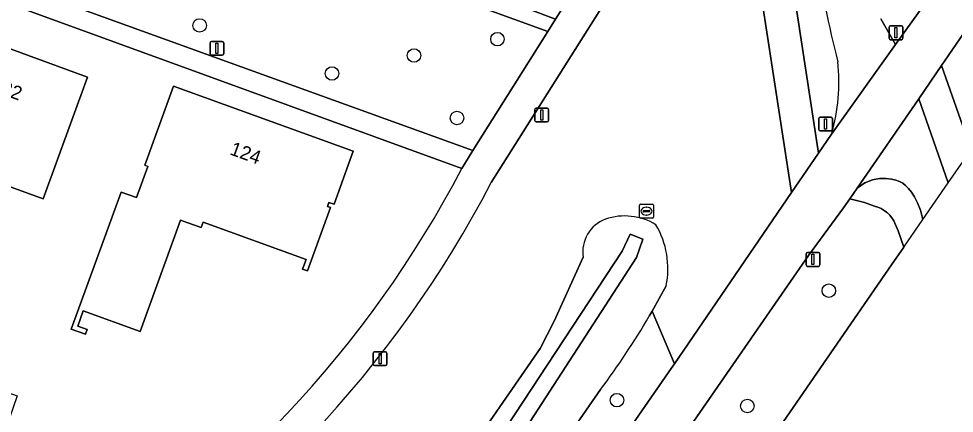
# Model space of a CAD drawing. Extents: x 155275 to 156265, y 382654 to 383635.
# Drawn here: x 156017.2 to 156085, y 382858.7 to 382887.3 of the extents above; entities that cross this region are included whole.
import ezdxf

# ---------------------------------------------------------------- set-up
doc = ezdxf.new("R2010")
doc.units = 0
for name, color, linetype in [('IMGEO_Berm_groen', 7, 'Continuous'), ('IMGEO_Boom', 7, 'Continuous'), ('IMGEO_Erf', 7, 'Continuous'), ('IMGEO_Fietspad_gesloten', 7, 'Continuous'), ('IMGEO_Groenvoorziening', 7, 'Continuous'), ('IMGEO_Lichtmast', 7, 'Continuous'), ('IMGEO_Loofbos', 7, 'Continuous'), ('IMGEO_Muur', 7, 'Continuous'), ('IMGEO_Oever', 7, 'Continuous'), ('IMGEO_Pand', 7, 'Continuous'), ('IMGEO_Pand_nummerreeks', 7, 'Continuous'), ('IMGEO_Rijbaan_lokaal_gesloten', 7, 'Continuous'), ('IMGEO_Rioolput', 7, 'Continuous'), ('IMGEO_Verkeersbordpaal', 7, 'Continuous'), ('IMGEO_Voetpad_open', 7, 'Continuous'), ('IMGEO_Waterloop', 7, 'Continuous')]:
    doc.layers.add(name, color=color, linetype=linetype)

msp = doc.modelspace()

# ---------------------------------------------------------------- linework, layer by layer
at = {"layer": 'IMGEO_Berm_groen'}
for points in [[(156079.66, 382887.343), (156080.716, 382885.461), (156082.651, 382888.154)], [(155986.514, 382749.083), (156014.734, 382790.495), (156047.177, 382837.009), (156064.466, 382861.974), (156064.698, 382862.314), (156063.065, 382866.115), (156062.862, 382865.755)], [(156059.34, 382860.43), (156000, 382774.875), (155980.085, 382745.904)]]:
    msp.add_lwpolyline(points, dxfattribs=at)
msp.add_lwpolyline([(156084.535, 382875.43), (156086.196, 382877.839), (156084.062, 382883.952), (156082.398, 382881.536)], close=True, dxfattribs=at)
msp.add_arc((156010.234, 382896.737), 61.071, 323.52277, 329.51525, dxfattribs=at)
at = {"layer": 'IMGEO_Boom'}
for centre in [(156030.272, 382886.856), (156051.859, 382885.857), (156045.814, 382884.671), (156039.869, 382883.369), (156048.927, 382880.135), (156075.884, 382867.609), (156060.522, 382859.665), (156069.98, 382859.243)]:
    msp.add_circle(centre, 0.489, dxfattribs=at)
at = {"layer": 'IMGEO_Erf'}
for points in [[(156045.075, 382959.998), (156041.929, 382961.201), (156013.02, 382971.678), (156002.893, 382944.069), (156002.495, 382942.881), (156019.157, 382936.752), (156019.126, 382936.628), (156034.624, 382930.96), (156034.689, 382931.086), (156052.26, 382924.735), (156049.961, 382918.346), (156000.148, 382936.433), (155991.066, 382911.384), (156005.755, 382906.062), (156030.725, 382896.891), (156056.081, 382887.309), (156064.322, 382900.379)], [(156049.271, 382876.469), (155986.733, 382899.275), (155985.513, 382896.209), (155977.474, 382874.314), (156011.194, 382862.059), (156017.047, 382859.976), (156014.804, 382853.502), (156014.672, 382853.55), (155989.659, 382862.664), (155989.671, 382862.757), (155975.249, 382867.763), (155964.586, 382839.123)]]:
    msp.add_lwpolyline(points, dxfattribs=at)
for points in [[(156018.937, 382874.268), (156011.075, 382877.127), (156008.041, 382868.784), (156006.026, 382869.517), (156008.951, 382877.562), (156009.749, 382877.272), (156009.857, 382877.57), (156009.742, 382877.612), (156012.953, 382886.451), (156022.145, 382883.089)], [(156025.959, 382864.645), (156021.842, 382866.141), (156021.443, 382865.041), (156022.129, 382864.792), (156022.003, 382864.444), (156020.969, 382864.82), (156024.582, 382874.764), (156025.691, 382874.361), (156026.515, 382876.626), (156026.298, 382876.704), (156028.389, 382882.456), (156041.398, 382877.728), (156040.023, 382873.884), (156039.649, 382874.017), (156039.541, 382873.718), (156039.757, 382873.639), (156038.092, 382869.045), (156037.734, 382869.175), (156037.987, 382869.871), (156030.525, 382872.583), (156030.381, 382872.188), (156029.423, 382872.537), (156028.896, 382872.728)]]:
    msp.add_lwpolyline(points, close=True, dxfattribs=at)
msp.add_arc((155979.211, 382912.976), 79.001, 300.67593, 332.47672, dxfattribs=at)
at = {"layer": 'IMGEO_Fietspad_gesloten'}
for points in [[(156082.398, 382881.536), (156084.062, 382883.952), (156086.982, 382888.192), (156088.437, 382890.305), (156091.194, 382894.308), (156094.99, 382899.819), (156096.461, 382901.955), (156095.373, 382906.504), (156091.11, 382900.353), (156089.894, 382898.497), (156087.194, 382894.668), (156085.596, 382892.423), (156082.651, 382888.154), (156080.716, 382885.461), (156076.075, 382878.967), (156075.126, 382877.579), (156073.179, 382874.729), (156064.698, 382862.314), (156064.466, 382861.974), (156047.177, 382837.009), (156014.734, 382790.495), (155986.514, 382749.083)], [(156076.075, 382878.967), (156080.716, 382885.461), (156079.66, 382887.343)], [(155984.634, 382740.15), (155989.627, 382747.079), (156025.11, 382799.188), (156066.088, 382858.148), (156074.411, 382870.169), (156076.941, 382873.612), (156077.401, 382874.28), (156077.93, 382875.048), (156082.398, 382881.536)], [(156082.709, 382872.779), (156084.535, 382875.43), (156082.398, 382881.536), (156077.93, 382875.048), (156078.493, 382875.43), (156079.039, 382875.649), (156079.552, 382875.74), (156080.017, 382875.743), (156080.418, 382875.694), (156080.744, 382875.622), (156081.011, 382875.528), (156081.237, 382875.404), (156081.442, 382875.24), (156081.647, 382875.031), (156081.866, 382874.765), (156082.094, 382874.425), (156082.317, 382873.994), (156082.526, 382873.452), (156082.708, 382872.781), (156082.709, 382872.779)]]:
    msp.add_lwpolyline(points, dxfattribs=at)
for centre, radius, start, end in [((156152.299, 382903.499), 78.179, 182.47954, 194.27589), ((156063.087, 382882.749), 13.527, 343.76588, 6.24853)]:
    msp.add_arc(centre, radius, start, end, dxfattribs=at)
at = {"layer": 'IMGEO_Groenvoorziening'}
for points in [[(156071.646, 382909.49), (156070.296, 382909.238), (156075.126, 382877.579), (156076.075, 382878.967)], [(156000, 382752.752), (156080.435, 382869.483), (156081.325, 382870.775), (156080.907, 382871.954), (156080.597, 382872.668), (156080.458, 382872.887), (156080.436, 382872.914), (156080.295, 382873.088), (156080.128, 382873.251), (156080.11, 382873.269), (156080.058, 382873.313), (156079.905, 382873.428), (156079.683, 382873.562), (156079.447, 382873.67), (156079.201, 382873.75), (156078.46, 382873.996), (156077.401, 382874.28), (156076.941, 382873.612), (156074.411, 382870.169), (156066.088, 382858.148)]]:
    msp.add_lwpolyline(points, dxfattribs=at)
for points in [[(156022.063, 382898.577), (156018.644, 382889.178), (156050.086, 382877.791), (156055.519, 382886.418)], [(156081.326, 382870.772), (156081.325, 382870.775), (156080.435, 382869.483), (156000, 382752.752), (156033.182, 382800.905)]]:
    msp.add_lwpolyline(points, close=True, dxfattribs=at)
for centre, radius, start, end in [((156152.299, 382903.499), 78.179, 182.47954, 194.27589), ((156063.087, 382882.749), 13.527, 343.76588, 6.24853)]:
    msp.add_arc(centre, radius, start, end, dxfattribs=at)
at = {"layer": 'IMGEO_Lichtmast'}
for p, q in [((156031.028, 382884.788), (156031.028, 382885.588)), ((156031.028, 382885.588), (156031.028, 382884.788)), ((156031.128, 382885.688), (156031.918, 382885.688)), ((156031.918, 382885.688), (156031.128, 382885.688)), ((156032.018, 382885.588), (156032.018, 382884.788)), ((156032.018, 382884.788), (156032.018, 382885.588)), ((156031.918, 382884.688), (156031.128, 382884.688)), ((156031.128, 382884.688), (156031.918, 382884.688)), ((156054.676, 382880.863), (156055.466, 382880.863)), ((156055.466, 382880.863), (156054.676, 382880.863)), ((156054.576, 382879.963), (156054.576, 382880.763)), ((156054.576, 382880.763), (156054.576, 382879.963)), ((156055.566, 382880.763), (156055.566, 382879.963)), ((156055.566, 382879.963), (156055.566, 382880.763)), ((156055.466, 382879.863), (156054.676, 382879.863)), ((156054.676, 382879.863), (156055.466, 382879.863)), ((156074.236, 382869.475), (156074.236, 382870.275)), ((156074.236, 382870.275), (156074.236, 382869.475)), ((156074.336, 382870.375), (156075.126, 382870.375)), ((156075.126, 382870.375), (156074.336, 382870.375)), ((156075.226, 382870.275), (156075.226, 382869.475)), ((156075.226, 382869.475), (156075.226, 382870.275)), ((156075.126, 382869.375), (156074.336, 382869.375)), ((156074.336, 382869.375), (156075.126, 382869.375)), ((156042.858, 382862.269), (156042.858, 382863.069)), ((156042.858, 382863.069), (156042.858, 382862.269)), ((156042.958, 382863.169), (156043.748, 382863.169)), ((156043.748, 382863.169), (156042.958, 382863.169)), ((156043.848, 382863.069), (156043.848, 382862.269)), ((156043.848, 382862.269), (156043.848, 382863.069)), ((156043.748, 382862.169), (156042.958, 382862.169)), ((156042.958, 382862.169), (156043.748, 382862.169))]:
    msp.add_line(p, q, dxfattribs=at)
for points in [[(156031.448, 382885.563), (156031.598, 382885.563), (156031.598, 382884.813), (156031.448, 382884.813), (156031.448, 382885.563)], [(156054.996, 382880.738), (156055.146, 382880.738), (156055.146, 382879.988), (156054.996, 382879.988), (156054.996, 382880.738)], [(156074.656, 382870.25), (156074.806, 382870.25), (156074.806, 382869.5), (156074.656, 382869.5), (156074.656, 382870.25)], [(156043.278, 382863.044), (156043.428, 382863.044), (156043.428, 382862.294), (156043.278, 382862.294), (156043.278, 382863.044)]]:
    msp.add_lwpolyline(points, dxfattribs=at)
for centre, start, end in [((156031.128, 382885.588), 90, 180), ((156031.128, 382885.588), 90, 180), ((156031.918, 382885.588), 0, 90), ((156031.918, 382885.588), 360, 90), ((156031.128, 382884.788), 180, 270), ((156031.128, 382884.788), 180, 270), ((156031.918, 382884.788), 270, 0), ((156031.918, 382884.788), 270, 0), ((156054.676, 382880.763), 90, 180), ((156054.676, 382880.763), 90, 180), ((156055.466, 382880.763), 0, 90), ((156055.466, 382880.763), 360, 90), ((156054.676, 382879.963), 180, 270), ((156054.676, 382879.963), 180, 270), ((156055.466, 382879.963), 270, 0), ((156055.466, 382879.963), 270, 0), ((156074.336, 382870.275), 90, 180), ((156074.336, 382870.275), 90, 180), ((156075.126, 382870.275), 0, 90), ((156075.126, 382870.275), 360, 90), ((156074.336, 382869.475), 180, 270), ((156074.336, 382869.475), 180, 270), ((156075.126, 382869.475), 270, 0), ((156075.126, 382869.475), 270, 0), ((156042.958, 382863.069), 90, 180), ((156042.958, 382863.069), 90, 180), ((156043.748, 382863.069), 0, 90), ((156043.748, 382863.069), 360, 90), ((156042.958, 382862.269), 180, 270), ((156042.958, 382862.269), 180, 270), ((156043.748, 382862.269), 270, 0), ((156043.748, 382862.269), 270, 0)]:
    msp.add_arc(centre, 0.1, start, end, dxfattribs=at)
at = {"layer": 'IMGEO_Loofbos'}
for points in [[(156064.098, 382867.956), (156063.065, 382866.115), (156064.698, 382862.314), (156073.179, 382874.729), (156069.286, 382900.053), (156068.696, 382903.893)], [(156066.49, 382899.37), (156051.412, 382875.466)], [(156054.965, 382863.418), (156055.977, 382865.399), (156058.076, 382870.033)], [(155934.35, 382725.505), (155936.692, 382725.864), (155940.946, 382726.618), (155945.166, 382727.826), (155948.196, 382728.914), (155951.784, 382730.315), (155954.364, 382731.6), (155958.769, 382734.001), (155962.634, 382736.652), (155965.967, 382739.079), (155968.671, 382741.394), (155972.439, 382745.646), (155978.599, 382754.24), (155980.796, 382757.16), (155986.725, 382765.837), (156000, 382783.894), (156054.965, 382863.418)]]:
    msp.add_lwpolyline(points, dxfattribs=at)
for centre, radius, start, end in [((155979.209, 382912.978), 81.366, 300.6869, 332.54647), ((156060.591, 382870.42), 2.545, 110.83809, 188.73927), ((156061.088, 382868.663), 4.366, 58.76089, 108.72343), ((156057.858, 382869.19), 6.361, 348.81162, 30.26365)]:
    msp.add_arc(centre, radius, start, end, dxfattribs=at)
at = {"layer": 'IMGEO_Muur'}
msp.add_lwpolyline([(156061.948, 382870.021), (156062.389, 382871.357), (156061.475, 382871.707), (156060.891, 382870.474)], dxfattribs=at)
at = {"layer": 'IMGEO_Oever'}
for points in [[(155978.096, 382748.892), (156032.148, 382826.737), (156060.891, 382870.474), (156061.475, 382871.707), (156062.389, 382871.357), (156061.948, 382870.021), (156039.407, 382835.215), (156018.939, 382805.285), (156004.138, 382783.88), (155988.541, 382761.444), (155979.267, 382747.908)], [(156058.076, 382870.033), (156055.977, 382865.399), (156054.965, 382863.418), (156000, 382783.894), (155986.725, 382765.837), (155980.796, 382757.16), (155978.599, 382754.24), (155972.439, 382745.646), (155968.671, 382741.394), (155965.967, 382739.079), (155962.634, 382736.652), (155958.769, 382734.001), (155954.364, 382731.6), (155951.784, 382730.315), (155948.196, 382728.914), (155945.166, 382727.826), (155940.946, 382726.618), (155936.692, 382725.864), (155934.35, 382725.505)], [(156062.862, 382865.755), (156063.065, 382866.115), (156064.098, 382867.956)], [(155980.085, 382745.904), (156000, 382774.875), (156059.34, 382860.43)]]:
    msp.add_lwpolyline(points, dxfattribs=at)
for centre, radius, start, end in [((156060.591, 382870.42), 2.545, 110.83809, 188.73927), ((156061.088, 382868.663), 4.366, 58.76089, 108.72343), ((156057.858, 382869.19), 6.361, 348.81162, 30.26365), ((156010.234, 382896.737), 61.071, 323.52277, 329.51525)]:
    msp.add_arc(centre, radius, start, end, dxfattribs=at)
at = {"layer": 'IMGEO_Pand'}
for points in [[(156022.145, 382883.089), (156012.953, 382886.451), (156009.742, 382877.612), (156009.857, 382877.57), (156011.075, 382877.127), (156018.937, 382874.268)], [(156022.003, 382864.444), (156022.129, 382864.792), (156021.443, 382865.041), (156021.842, 382866.141), (156025.959, 382864.645), (156028.896, 382872.728), (156029.423, 382872.537), (156030.381, 382872.188), (156030.525, 382872.583), (156037.987, 382869.871), (156037.734, 382869.175), (156038.092, 382869.045), (156039.757, 382873.639), (156039.541, 382873.718), (156039.649, 382874.017), (156040.023, 382873.884), (156041.398, 382877.728), (156028.389, 382882.456), (156026.298, 382876.704), (156026.515, 382876.626), (156025.691, 382874.361), (156024.582, 382874.764), (156020.969, 382864.82)]]:
    msp.add_lwpolyline(points, close=True, dxfattribs=at)
at = {"layer": 'IMGEO_Rijbaan_lokaal_gesloten'}
msp.add_lwpolyline([(156086.196, 382877.839), (156088.862, 382881.709), (156086.982, 382888.192), (156084.062, 382883.952)], close=True, dxfattribs=at)
at = {"layer": 'IMGEO_Rioolput'}
for p, q in [((156062.165, 382872.952), (156062.165, 382873.804)), ((156062.24, 382873.878), (156063.092, 382873.878)), ((156062.424, 382873.372), (156062.424, 382873.384)), ((156062.467, 382873.421), (156062.865, 382873.421)), ((156062.653, 382873.658), (156062.678, 382873.658)), ((156062.908, 382873.384), (156062.908, 382873.372)), ((156063.166, 382873.804), (156063.166, 382872.952)), ((156063.092, 382872.878), (156062.24, 382872.878)), ((156062.862, 382873.335), (156062.464, 382873.335)), ((156062.676, 382873.098), (156062.651, 382873.098))]:
    msp.add_line(p, q, dxfattribs=at)
for points in [[(156062.165, 382872.952), (156062.165, 382873.804)], [(156062.24, 382873.878), (156063.092, 382873.878)], [(156063.166, 382873.804), (156063.166, 382872.952)], [(156063.092, 382872.878), (156062.24, 382872.878)]]:
    msp.add_lwpolyline(points, dxfattribs=at)
for centre, radius, start, end in [((156062.242, 382873.802), 0.0765, 91.55205, 178.44795), ((156062.242, 382873.802), 0.0765, 91.55205, 178.44795), ((156062.464, 382873.381), 0.0403, 85.87752, 175.75265), ((156062.461, 382873.371), 0.0366, 178.93798, 274.71019), ((156062.865, 382873.378), 0.043, 264.86636, 352.45326), ((156062.869, 382873.383), 0.0386, 1.73085, 96.63898), ((156063.09, 382873.802), 0.0765, 1.55205, 88.44795), ((156063.09, 382873.802), 0.0765, 1.55205, 88.44795), ((156062.242, 382872.954), 0.0765, 181.55205, 268.44795), ((156062.242, 382872.954), 0.0765, 181.55205, 268.44795), ((156063.09, 382872.954), 0.0765, 271.55205, 358.44795), ((156063.09, 382872.954), 0.0765, 271.55205, 358.44795)]:
    msp.add_arc(centre, radius, start, end, dxfattribs=at)
for centre, major_axis, ratio, start_param, end_param in [((156062.652, 382873.378), (-0.387, 0.002), 0.722429, 4.712389, 7.853982), ((156062.677, 382873.378), (-0.39, 0.002), 0.717154, 1.570796, 4.712389)]:
    msp.add_ellipse(centre, major_axis=major_axis, ratio=ratio, start_param=start_param, end_param=end_param, dxfattribs=at)
at = {"layer": 'IMGEO_Verkeersbordpaal'}
for p, q in [((156080.254, 382885.921), (156080.254, 382886.721)), ((156080.254, 382886.721), (156080.254, 382885.921)), ((156080.354, 382886.821), (156081.144, 382886.821)), ((156081.144, 382886.821), (156080.354, 382886.821)), ((156081.244, 382886.721), (156081.244, 382885.921)), ((156081.244, 382885.921), (156081.244, 382886.721)), ((156081.144, 382885.821), (156080.354, 382885.821)), ((156080.354, 382885.821), (156081.144, 382885.821)), ((156075.251, 382880.195), (156076.041, 382880.195)), ((156076.041, 382880.195), (156075.251, 382880.195)), ((156075.151, 382879.295), (156075.151, 382880.095)), ((156075.151, 382880.095), (156075.151, 382879.295)), ((156076.141, 382880.095), (156076.141, 382879.295)), ((156076.141, 382879.295), (156076.141, 382880.095)), ((156076.041, 382879.195), (156075.251, 382879.195)), ((156075.251, 382879.195), (156076.041, 382879.195))]:
    msp.add_line(p, q, dxfattribs=at)
for points in [[(156080.674, 382886.696), (156080.824, 382886.696), (156080.824, 382885.946), (156080.674, 382885.946), (156080.674, 382886.696)], [(156075.571, 382880.07), (156075.721, 382880.07), (156075.721, 382879.32), (156075.571, 382879.32), (156075.571, 382880.07)]]:
    msp.add_lwpolyline(points, dxfattribs=at)
for centre, start, end in [((156080.354, 382886.721), 90, 180), ((156080.354, 382886.721), 90, 180), ((156081.144, 382886.721), 0, 90), ((156081.144, 382886.721), 360, 90), ((156080.354, 382885.921), 180, 270), ((156080.354, 382885.921), 180, 270), ((156081.144, 382885.921), 270, 0), ((156081.144, 382885.921), 270, 0), ((156075.251, 382880.095), 90, 180), ((156075.251, 382880.095), 90, 180), ((156076.041, 382880.095), 0, 90), ((156076.041, 382880.095), 360, 90), ((156075.251, 382879.295), 180, 270), ((156075.251, 382879.295), 180, 270), ((156076.041, 382879.295), 270, 0), ((156076.041, 382879.295), 270, 0)]:
    msp.add_arc(centre, 0.1, start, end, dxfattribs=at)
at = {"layer": 'IMGEO_Voetpad_open'}
for points in [[(156070.296, 382909.238), (156068.696, 382903.893), (156069.286, 382900.053), (156073.179, 382874.729), (156075.126, 382877.579)], [(156081.326, 382870.772), (156082.709, 382872.779), (156082.708, 382872.781), (156082.526, 382873.452), (156082.317, 382873.994), (156082.094, 382874.425), (156081.866, 382874.765), (156081.647, 382875.031), (156081.442, 382875.24), (156081.237, 382875.404), (156081.011, 382875.528), (156080.744, 382875.622), (156080.418, 382875.694), (156080.017, 382875.743), (156079.552, 382875.74), (156079.039, 382875.649), (156078.493, 382875.43), (156077.93, 382875.048), (156077.401, 382874.28), (156078.46, 382873.996), (156079.201, 382873.75), (156079.447, 382873.67), (156079.683, 382873.562), (156079.905, 382873.428), (156080.058, 382873.313), (156080.11, 382873.269), (156080.128, 382873.251), (156080.295, 382873.088), (156080.436, 382872.914), (156080.458, 382872.887), (156080.597, 382872.668), (156080.907, 382871.954), (156081.325, 382870.775)]]:
    msp.add_lwpolyline(points, close=True, dxfattribs=at)
for points in [[(156013.237, 382901.777), (156020.768, 382899.059), (156022.063, 382898.577), (156055.519, 382886.418), (156056.081, 382887.309), (156030.725, 382896.891), (156005.755, 382906.062)], [(156064.322, 382900.379), (156056.081, 382887.309), (156055.519, 382886.418), (156050.086, 382877.791), (156049.271, 382876.469)], [(155986.733, 382899.275), (156049.271, 382876.469), (156050.086, 382877.791), (156018.644, 382889.178), (156017.337, 382889.666), (156009.825, 382892.366)], [(156051.412, 382875.466), (156066.49, 382899.37)]]:
    msp.add_lwpolyline(points, dxfattribs=at)
for centre, radius, start, end in [((155979.211, 382912.976), 79.001, 300.67593, 332.47672), ((155979.209, 382912.978), 81.366, 300.6869, 332.54647)]:
    msp.add_arc(centre, radius, start, end, dxfattribs=at)
at = {"layer": 'IMGEO_Waterloop'}
msp.add_lwpolyline([(155979.267, 382747.908), (155988.541, 382761.444), (156004.138, 382783.88), (156018.939, 382805.285), (156039.407, 382835.215), (156061.948, 382870.021), (156062.389, 382871.357), (156061.475, 382871.707), (156060.891, 382870.474), (156032.148, 382826.737), (155978.096, 382748.892)], dxfattribs=at)

# ---------------------------------------------------------------- texts
at = {"layer": 'IMGEO_Pand_nummerreeks'}
for s, rotation, p in [('122', 339.8548, (156015.083, 382882.16)), ('124', 340.02834, (156032.396, 382877.51))]:
    msp.add_text(s, height=1, rotation=rotation, dxfattribs=at).set_placement(p)

doc.saveas('drawing.dxf')
